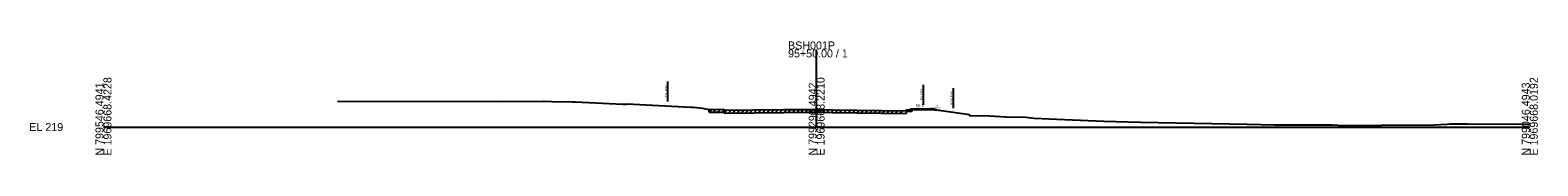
# Model space of a CAD drawing. Extents: x 1979833 to 1982361, y 790388 to 810009.
# Drawn here: x 1981583 to 1982111, y 796888 to 796928 of the extents above; entities that cross this region are included whole.
import ezdxf

# ---------------------------------------------------------------- set-up
doc = ezdxf.new("R2010")
doc.units = 0
for name, color, linetype in [('Default', 7, 'Continuous'), ('RD_GPK_XS_Cell', 7, 'Continuous'), ('RD_Sketch1', 7, 'Continuous'), ('RD_XS_CurbBase', 7, 'Continuous'), ('RD_XS_ExGround', 7, 'Continuous'), ('RD_XS_ExPaveRet', 7, 'Continuous'), ('RD_XS_ExRW', 7, 'Continuous'), ('RD_XS_Greenside', 7, 'Continuous'), ('RD_XS_NewRW', 7, 'Continuous'), ('RD_XS_PaveOvlay', 7, 'Continuous'), ('RD_XS_SW', 7, 'Continuous'), ('RD_XS_SWbase', 7, 'Continuous'), ('RD_XS_TieSlope', 7, 'Continuous'), ('RD_XS_TX_Slope', 7, 'Continuous')]:
    doc.layers.add(name, color=color, linetype=linetype)

msp = doc.modelspace()

# ---------------------------------------------------------------- linework, layer by layer
at = {"layer": 'RD_GPK_XS_Cell'}
for p, q in [((1981858.57, 796897.73), (1981858.57, 796924.94)), ((1981608.57, 796897.73), (1981858.57, 796897.73)), ((1981858.57, 796897.73), (1982108.57, 796897.73))]:
    msp.add_line(p, q, dxfattribs=at)
at = {"layer": 'RD_XS_CurbBase'}
msp.add_line((1981889.97, 796903.72), (1981889.97, 796903.22), dxfattribs=at)
for points in [[(1981889.97, 796903.72), (1981891.39, 796903.63), (1981891.47, 796904.13), (1981891.97, 796904.13)], [(1981891.97, 796903.13), (1981891.39, 796903.13), (1981889.97, 796903.22)], [(1981891.97, 796904.13), (1981891.97, 796903.13)]]:
    msp.add_lwpolyline(points, dxfattribs=at)
at = {"layer": 'RD_XS_ExGround'}
msp.add_lwpolyline([(1981690.59, 796906.8), (1981748.44, 796906.74), (1981762.88, 796906.75), (1981763.18, 796906.76), (1981765.71, 796906.69), (1981772.98, 796906.55), (1981773.88, 796906.54), (1981790.68, 796905.79), (1981791.22, 796905.76), (1981791.83, 796905.71), (1981792.13, 796905.89), (1981814.44, 796904.75), (1981815.43, 796904.71), (1981818.48, 796904.35), (1981820.86, 796903.93), (1981824.46, 796903.95), (1981826.04, 796903.9), (1981826.14, 796903.6), (1981847.02, 796903.83), (1981857.58, 796903.93), (1981858.57, 796903.91), (1981864.16, 796903.82), (1981889.97, 796903.44), (1981890.07, 796903.74), (1981892.03, 796903.83), (1981892.79, 796903.79), (1981894.54, 796903.98), (1981894.93, 796903.99), (1981895.46, 796904.01), (1981897.65, 796903.91), (1981899.76, 796903.71), (1981901.28, 796903.61), (1981903.17, 796903.36), (1981910.55, 796902.35), (1981911.3, 796902.24), (1981912.08, 796902.07), (1981912.18, 796901.77), (1981919.15, 796901.63), (1981924.86, 796901.34), (1981931.96, 796901.18), (1981934.88, 796900.82), (1981940.14, 796900.6), (1981959.23, 796899.81), (1981972.15, 796899.44), (1981978.4, 796899.31), (1982009.53, 796898.72), (1982019.05, 796898.52), (1982032.04, 796898.48), (1982039.33, 796898.45), (1982043.4, 796898.32), (1982056.52, 796898.36), (1982075.06, 796898.48), (1982079.63, 796898.73), (1982080.61, 796898.8), (1982086.74, 796898.86), (1982105.06, 796898.79), (1982108.57, 796898.88)], dxfattribs=at)
at = {"layer": 'RD_XS_ExPaveRet'}
for p, q in [((1981820.86, 796902.93), (1981821.87, 796903.93)), ((1981820.86, 796902.93), (1981820.86, 796903.93)), ((1981820.86, 796902.93), (1981824.46, 796902.95)), ((1981822.36, 796902.94), (1981823.37, 796903.94)), ((1981823.86, 796902.94), (1981824.85, 796903.94)), ((1981824.46, 796902.95), (1981825.84, 796902.91)), ((1981825.84, 796903.91), (1981825.84, 796902.91)), ((1981826.14, 796902.6), (1981827.15, 796903.61)), ((1981826.14, 796902.6), (1981826.14, 796903.6)), ((1981826.14, 796902.6), (1981847.02, 796902.83)), ((1981827.64, 796902.62), (1981828.65, 796903.63)), ((1981829.14, 796902.63), (1981830.15, 796903.64)), ((1981830.64, 796902.65), (1981831.65, 796903.66)), ((1981832.14, 796902.67), (1981833.15, 796903.68)), ((1981833.64, 796902.68), (1981834.65, 796903.69)), ((1981835.14, 796902.7), (1981836.15, 796903.71)), ((1981836.64, 796902.72), (1981837.65, 796903.73)), ((1981838.14, 796902.73), (1981839.15, 796903.74)), ((1981839.64, 796902.75), (1981840.65, 796903.76)), ((1981841.14, 796902.77), (1981842.15, 796903.78)), ((1981842.64, 796902.78), (1981843.65, 796903.79)), ((1981844.14, 796902.8), (1981845.15, 796903.81)), ((1981845.64, 796902.82), (1981846.65, 796903.83)), ((1981847.02, 796902.83), (1981857.58, 796902.93)), ((1981847.14, 796902.83), (1981848.15, 796903.84)), ((1981848.64, 796902.85), (1981849.65, 796903.86)), ((1981850.14, 796902.86), (1981851.15, 796903.87)), ((1981851.64, 796902.88), (1981852.65, 796903.88)), ((1981853.14, 796902.89), (1981854.15, 796903.9)), ((1981854.64, 796902.9), (1981855.65, 796903.91)), ((1981856.14, 796902.92), (1981857.15, 796903.93)), ((1981857.58, 796902.93), (1981858.57, 796902.91)), ((1981857.64, 796902.93), (1981858.63, 796903.91)), ((1981858.57, 796902.91), (1981864.16, 796902.82)), ((1981859.14, 796902.9), (1981860.13, 796903.89)), ((1981860.64, 796902.88), (1981861.63, 796903.86)), ((1981862.14, 796902.85), (1981863.13, 796903.83)), ((1981863.64, 796902.83), (1981864.63, 796903.81)), ((1981864.16, 796902.82), (1981889.97, 796902.44)), ((1981865.14, 796902.8), (1981866.13, 796903.79)), ((1981866.64, 796902.78), (1981867.63, 796903.77)), ((1981868.14, 796902.76), (1981869.13, 796903.74)), ((1981869.64, 796902.74), (1981870.63, 796903.72)), ((1981871.14, 796902.72), (1981872.13, 796903.7)), ((1981872.64, 796902.69), (1981873.63, 796903.68)), ((1981874.14, 796902.67), (1981875.13, 796903.66)), ((1981875.64, 796902.65), (1981876.63, 796903.64)), ((1981877.14, 796902.63), (1981878.13, 796903.61)), ((1981878.64, 796902.61), (1981879.63, 796903.59)), ((1981880.14, 796902.58), (1981881.13, 796903.57)), ((1981881.64, 796902.56), (1981882.63, 796903.55)), ((1981883.14, 796902.54), (1981884.13, 796903.53)), ((1981884.64, 796902.52), (1981885.63, 796903.51)), ((1981886.14, 796902.5), (1981887.13, 796903.48)), ((1981887.64, 796902.48), (1981888.63, 796903.46)), ((1981889.97, 796903.44), (1981889.97, 796902.44))]:
    msp.add_line(p, q, dxfattribs=at)
at = {"layer": 'RD_XS_ExRW'}
for p, q in [((1981806.4, 796906.66), (1981806.4, 796913.66)), ((1981895.99, 796905.48), (1981895.99, 796912.48))]:
    msp.add_line(p, q, dxfattribs=at)
at = {"layer": 'RD_XS_Greenside'}
msp.add_lwpolyline([(1981898.59, 796904.27), (1981899.59, 796904.29)], dxfattribs=at)
at = {"layer": 'RD_XS_NewRW'}
msp.add_line((1981906.57, 796904.38), (1981906.57, 796911.38), dxfattribs=at)
at = {"layer": 'RD_XS_PaveOvlay'}
msp.add_line((1981889.97, 796903.74), (1981889.97, 796903.72), dxfattribs=at)
at = {"layer": 'RD_XS_SW'}
msp.add_lwpolyline([(1981891.97, 796904.13), (1981898.59, 796904.27)], dxfattribs=at)
at = {"layer": 'RD_XS_SWbase'}
for points in [[(1981891.97, 796903.8), (1981898.59, 796903.93)], [(1981898.59, 796903.93), (1981898.59, 796904.27)]]:
    msp.add_lwpolyline(points, dxfattribs=at)
at = {"layer": 'RD_XS_TieSlope'}
msp.add_lwpolyline([(1981899.59, 796904.29), (1981900.89, 796903.64)], dxfattribs=at)

# ---------------------------------------------------------------- texts
at = {"layer": 'Default'}
msp.add_text('-', height=0.0001, dxfattribs=at).set_placement((1981608.57, 796897.73))
at = {"layer": 'RD_GPK_XS_Cell'}
for s, p in [('BSH001P', (1981848.57, 796924.94)), ('95+50.00 / 1', (1981848.57, 796922.14)), ('EL 219', (1981582.57, 796896.33))]:
    msp.add_text(s, height=2.8, dxfattribs=at).set_placement(p)
for s, p in [('N 799546.4941', (1981608.57, 796887.73)), ('E 1969668.4228', (1981611.37, 796887.73)), ('N 799296.4942', (1981858.57, 796887.73)), ('E 1969668.2210', (1981861.37, 796887.73)), ('N 799046.4943', (1982108.57, 796887.73)), ('E 1969668.0192', (1982111.37, 796887.73))]:
    msp.add_text(s, height=2.8, rotation=90, dxfattribs=at).set_placement(p)
at = {"layer": 'RD_Sketch1'}
for s, height, p in [('225.18', 0.025, (1981858.57, 796903.89)), ('R_ES1', 0.01, (1981899.57, 796904.28))]:
    msp.add_text(s, height=height, dxfattribs=at).set_placement(p)
at = {"layer": 'RD_XS_ExRW'}
for p in [(1981806.15, 796908.35), (1981895.74, 796907.17)]:
    msp.add_text('EX. R/W ', height=0.75, rotation=90, dxfattribs=at).set_placement(p)
at = {"layer": 'RD_XS_NewRW'}
msp.add_text('NEW R/W ', height=0.75, rotation=90, dxfattribs=at).set_placement((1981906.32, 796905.52))
at = {"layer": 'RD_XS_TX_Slope'}
for s, rotation, p in [('50:1', 1.1458, (1981893.31, 796904.66)), ('2:1', 333.4349, (1981900.08, 796904.5))]:
    msp.add_text(s, height=1, rotation=rotation, dxfattribs=at).set_placement(p)

doc.saveas('drawing.dxf')
